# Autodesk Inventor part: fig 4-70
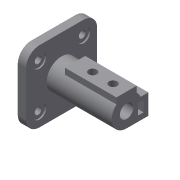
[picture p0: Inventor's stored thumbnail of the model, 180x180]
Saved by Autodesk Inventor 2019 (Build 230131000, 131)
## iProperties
Shininess: 77.0
Length Units: 11269
Angle Units: 11279
Time Units: 11290
Mass Units: 11283
Length Display Precision: 3
Angle Display Precision: 2
Created: 2001-12
Part Number: fig 4-70
Document SubType Name: Modeling
Designer: Renu Muthoo
Density: 1 g/cm^3
Material: Generic
Appearance: Default
Density: 0.0
Volumn: 0.0
Area: 0.0
PropertySet Name: Model Information
Control State: 0
Master: False
Checked Out: False
Author: Renu Muthoo
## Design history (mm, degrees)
node "Sketch1"
sketch "Sketch2"
  geometry: L1 (24.44, 30.488)-(-40.56, 30.488); L2 (-60.56, 10.488)-(-60.56, -54.512); L3 (-40.56, -74.512)-(24.44, -74.512); L4 (44.44, -54.512)-(44.44, 10.488); A1 r 20 centre (24.44, 10.488) between (44.44, 10.488) and (24.44, 30.488); A2 r 20 centre (-40.56, 10.488) between (-40.56, 30.488) and (-60.56, 10.488); A3 r 20 centre (-40.56, -54.512) between (-60.56, -54.512) and (-40.56, -74.512); A4 r 20 centre (24.44, -54.512) between (24.44, -74.512) and (44.44, -54.512); 2 further points
  constraints: 8 end point, 8 point on circle, 8 tangent, 4 centre point, 4 point on line, 3 equal radius, 2 parallel, 2 perpendicular, 1 horizontal
  dimensions: "d1" = 20 radius of A1; "d2" = 105 distance between parallel lines of L2 L4
extrude "Extrusion1" new body sketch "Sketch2" distance "d3" = 12; taper "d4" = 0 deg
sketch "Sketch3"
  geometry: A1 r 20 centre (-24.44, 10.488) between (-24.44, 30.488) and (-44.44, 10.488) reference; A2 r 20 centre (-24.44, -54.512) between (-44.44, -54.512) and (-24.44, -74.512) reference; A3 r 20 centre (40.56, -54.512) between (40.56, -74.512) and (60.56, -54.512) reference; A4 r 20 centre (40.56, 10.488) between (60.56, 10.488) and (40.56, 30.488) reference
hole "Hole1" sketch "Sketch3" at (-24.44, 10.488), (-24.44, -54.512), (40.56, 10.488), (40.56, -54.512) diameter "d5" = 10; stored, may be unused: countersink angle "d9" = 82 deg, drill point angle "d11" = 118 deg; dims "d6" = 6, "d7" = 20, "d8" = 2, "d10" = 8
sketch "Sketch4"
  geometry: L1 (-24.44, 30.488)-(40.56, 30.488) reference; L2 (-44.44, -54.512)-(-44.44, 10.488) reference; C1 r 22 at (8.06, -22.012)
  constraints: 1 centre point
  dimensions: "d12" = 52.5 distance from line of L2 C1.centre; "d13" = 52.5 distance from line of L1 C1.centre; "d14" = 44 diameter of C1
extrude "Extrusion2" join sketch "Sketch4" distance "d15" = 96; taper "d16" = 0 deg
sketch "Sketch5"
  geometry: L1 (-15, 16.093)-(15, 16.093); L2 (15, 16.093)-(15, 25); L3 (15, 25)-(-15, 25); L4 (-15, 25)-(-15, 16.093); 1 further point
  constraints: 8 end point, 2 parallel, 1 horizontal, 1 perpendicular, 2 other
  dimensions: "d17" = 30 distance of L2.end L3.end; "d18" = 25 distance from line of point (0, 0) L3; "d19" = 15 distance from line of point (0, 0) L4
extrude "Extrusion3" join sketch "Sketch5" distance "d20" = 76; taper "d21" = 0 deg
sketch "Sketch6"
  geometry: L1 (8, -44.012)-(40.06, -44.012); L2 (40.06, -44.012)-(40.06, -14.012); L3 (40.06, -14.012)-(8, -14.012); L4 (8, -14.012)-(8, -44.012); A1 r 22 centre (8.06, -22.012) between (-6.94, -5.918) and (23.06, -5.918) reference
  constraints: 8 end point, 2 parallel, 1 horizontal, 1 perpendicular, 1 tangent
  dimensions: "d22" = 32 distance from line of A1.centre L2; "d23" = 30 distance of L1.end L2.end
extrude "Extrusion4" join sketch "Sketch6" distance "d24" = 57; taper "d25" = 0 deg
sketch "Sketch7"
  geometry: L1 (25.06, -20.012)-(33.06, -20.012); L2 (33.06, -20.012)-(33.06, -36.012); L3 (33.06, -36.012)-(25.06, -36.012); L4 (25.06, -36.012)-(25.06, -20.012); A1 r 22 centre (8.06, -22.012) between (-6.94, -5.918) and (8, -44.012) reference
  constraints: 8 end point, 2 parallel, 1 horizontal, 1 perpendicular
  dimensions: "d26" = 8 distance of L2.end L3.end; "d27" = 16 distance of L1.end L2.end; "d28" = 25 distance from line of A1.centre L2; "d29" = 2 vertical distance of A1.centre L1.start
extrude "Extrusion5" cut sketch "Sketch7" distance "d30" = 35; taper "d31" = 0 deg
sketch "Sketch8"
  geometry: A1 r 22 centre (8.06, -22.012) between (-6.94, -5.918) and (8, -44.012) reference
hole "Hole2" sketch "Sketch8" at (8.06, -22.012) diameter "d32" = 20; stored, may be unused: countersink angle "d36" = 82 deg, drill point angle "d38" = 0 deg; dims "d33" = 6, "d34" = 20, "d35" = 2, "d37" = 96
sketch "Sketch9"
  geometry: L1 (0, 0)-(0, 76) reference; L2 (30, 0)-(0, 0) reference; 2 further points
  dimensions: "d39" = 20 distance from line of L2 point (15, 20); "d40" = 15 distance from line of L1 point (15, 20); "d41" = 30 distance of point (15, 50) point (15, 20)
hole "Hole3" sketch "Sketch9" at (15, 20), (15, 50) diameter "d42" = 12; stored, may be unused: countersink angle "d46" = 82 deg, drill point angle "d48" = 0 deg; dims "d43" = 6, "d44" = 20, "d45" = 2, "d47" = 25
sketch "Sketch10"
  geometry: L1 (30, 0)-(0, 0) reference; L2 (30, 0)-(30, 57) reference; 2 further points
  dimensions: "d49" = 15 distance from line of L1 point (15, 15); "d50" = 15 distance from line of L2 point (15, 15); "d51" = 22 distance of point (15, 37) point (15, 15)
hole "Hole4" sketch "Sketch10" at (15, 15), (15, 37) diameter "d52" = 10; stored, may be unused: countersink angle "d56" = 82 deg, drill point angle "d58" = 0 deg; dims "d53" = 6, "d54" = 20, "d55" = 2, "d57" = 7
body "Solid1"
